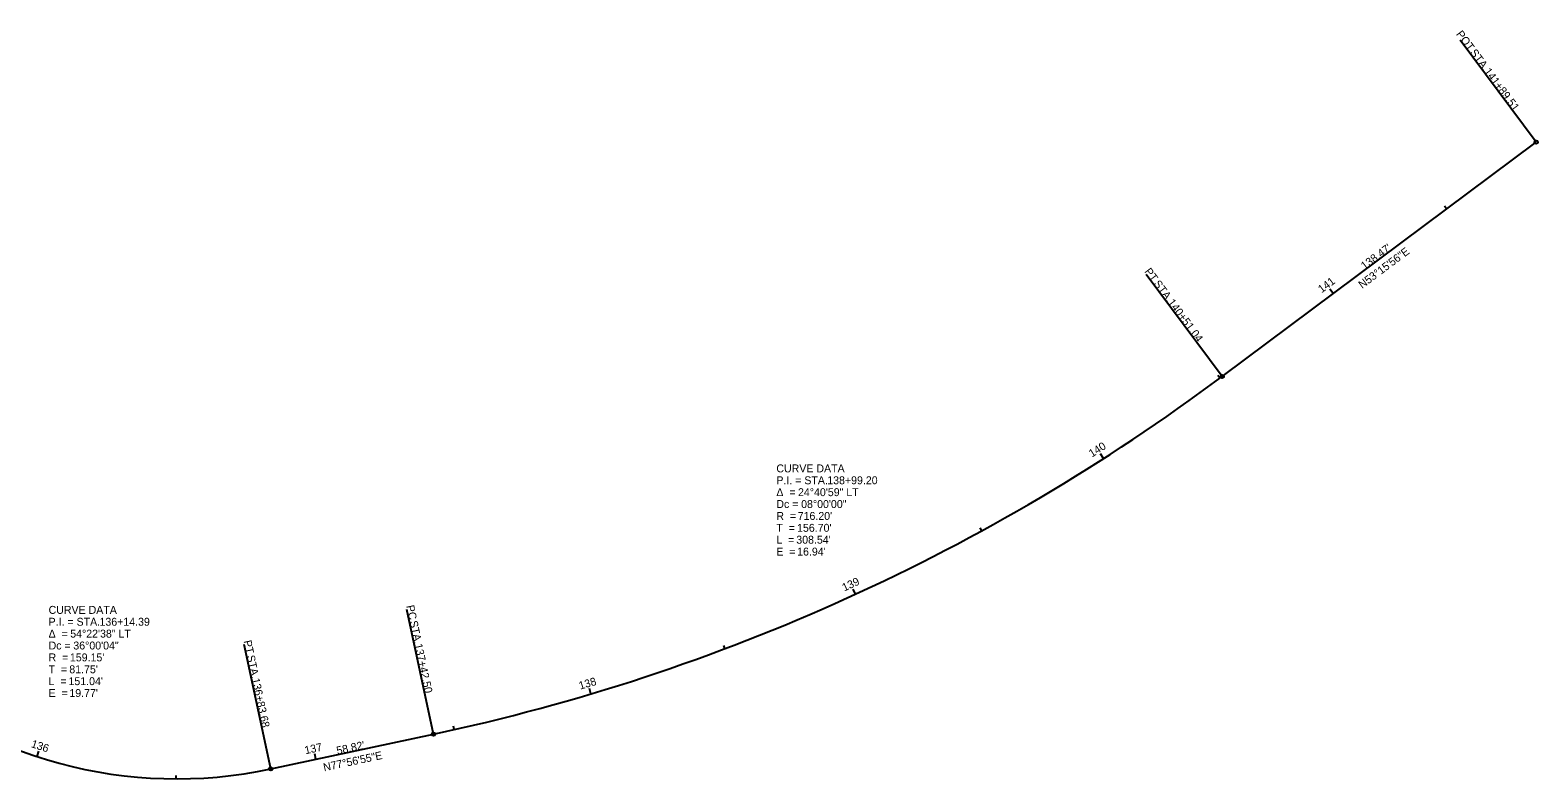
# Model space of a CAD drawing. Extents: x 1926907 to 1928253, y 199360 to 200380.
# Drawn here: x 1927721 to 1928253, y 199720 to 199984 of the extents above; entities that cross this region are included whole.
import ezdxf

# ---------------------------------------------------------------- set-up
doc = ezdxf.new("R2010")
doc.units = 0
for name, color, linetype in [('RW_X_CL', 7, 'Continuous'), ('RW_X_CL_100_Bearings', 7, 'Continuous'), ('RW_X_CL_100_Cardinal_Points', 7, 'Continuous'), ('RW_X_CL_100_Curve_Data', 7, 'Continuous'), ('RW_X_CL_100_Distances', 7, 'Continuous'), ('RW_X_CL_100_Stations', 7, 'Continuous')]:
    doc.layers.add(name, color=color, linetype=linetype)

msp = doc.modelspace()

# ---------------------------------------------------------------- linework, layer by layer
at = {"layer": 'RW_X_CL'}
for p, q in [((1928141.93, 199862.1), (1928252.9, 199944.92)), ((1927805.57, 199723.38), (1927863.1, 199735.66))]:
    msp.add_line(p, q, dxfattribs=at)
for centre, radius, start, end in [((1927713.56, 200436.07), 716.2, 282.05144, 306.73454), ((1927772.34, 199879.02), 159.15, 227.6743, 282.0514)]:
    msp.add_arc(centre, radius, start, end, dxfattribs=at)
at = {"layer": 'RW_X_CL_100_Cardinal_Points'}
for p, q in [((1928252.9, 199944.92), (1928225.98, 199980.98)), ((1928141.93, 199862.1), (1928115.01, 199898.16)), ((1927863.1, 199735.66), (1927853.7, 199779.67)), ((1927805.57, 199723.38), (1927796.18, 199767.39))]:
    msp.add_line(p, q, dxfattribs=at)
for centre in [(1928252.9, 199944.92), (1928141.93, 199862.1), (1927863.1, 199735.66), (1927805.57, 199723.38)]:
    msp.add_circle(centre, 0.6, dxfattribs=at)
at = {"layer": 'RW_X_CL_100_Stations'}
for p, q in [((1928221.23, 199921.29), (1928220.51, 199922.25)), ((1928181.16, 199891.38), (1928179.96, 199892.98)), ((1928141.09, 199861.48), (1928140.37, 199862.44)), ((1928099.97, 199833.05), (1928098.89, 199834.74)), ((1928056.96, 199807.57), (1928056.39, 199808.62)), ((1928012.28, 199785.15), (1928011.45, 199786.96)), ((1927966.15, 199765.89), (1927965.72, 199767.02)), ((1927918.78, 199749.91), (1927918.21, 199751.82)), ((1927870.42, 199737.26), (1927870.16, 199738.43)), ((1927722.96, 199727.72), (1927723.58, 199729.63)), ((1927821.53, 199726.78), (1927821.11, 199728.74)), ((1927772.14, 199719.87), (1927772.14, 199721.07))]:
    msp.add_line(p, q, dxfattribs=at)

# ---------------------------------------------------------------- texts
at = {"layer": 'RW_X_CL_100_Bearings'}
for s, rotation, p in [('N53°15\'56"E', 36.7345, (1928191.37, 199893.01)), ('N77°56\'55"E', 12.0514, (1927824.46, 199722.5))]:
    msp.add_text(s, height=2.8, rotation=rotation, dxfattribs=at).set_placement(p)
at = {"layer": 'RW_X_CL_100_Cardinal_Points'}
for s, rotation, p in [('POT', 306.7345, (1928224.48, 199983.06)), (' STA. ', 306.7345, (1928228.75, 199977.34)), ('141+89.51', 306.7345, (1928234.32, 199969.87)), ('PT', 306.7345, (1928114.31, 199899.17)), (' STA. ', 306.7345, (1928116.91, 199895.68)), ('140+51.04', 306.7345, (1928122.49, 199888.21)), ('PC', 282.0514, (1927853.46, 199780.98)), (' STA. ', 282.0514, (1927854.42, 199776.48)), ('PT', 282.0514, (1927795.96, 199768.56)), ('137+42.50', 282.0514, (1927856.36, 199767.37)), (' STA. ', 282.0514, (1927796.87, 199764.31)), ('136+83.68', 282.0514, (1927798.82, 199755.19))]:
    msp.add_text(s, height=2.8, rotation=rotation, dxfattribs=at).set_placement(p)
at = {"layer": 'RW_X_CL_100_Curve_Data'}
for s, p in [('CURVE DATA', (1927984.31, 199828.19)), ('P.I. = STA. ', (1927984.31, 199823.99)), ('138+99.20', (1928002.3, 199823.99)), ('Δ  = ', (1927984.31, 199819.79)), ('24°40\'59" LT', (1927991.96, 199819.79)), ('Dc = ', (1927984.31, 199815.59)), ('R  = ', (1927984.31, 199811.39)), ("716.20'", (1927991.85, 199811.39)), ('08°00\'00"', (1927993.06, 199815.59)), ('T  = ', (1927984.31, 199807.19)), ("156.70'", (1927991.63, 199807.19)), ('L  = ', (1927984.31, 199802.99)), ("308.54'", (1927991.35, 199802.99)), ('E  = ', (1927984.31, 199798.79)), ("16.94'", (1927991.66, 199798.79)), ('CURVE DATA', (1927727.04, 199778.19)), ('P.I. = STA. ', (1927727.04, 199773.99)), ('136+14.39', (1927745.03, 199773.99)), ('Δ  = ', (1927727.04, 199769.79)), ('54°22\'38" LT', (1927734.68, 199769.79)), ('Dc = ', (1927727.04, 199765.59)), ('36°00\'04"', (1927735.78, 199765.59)), ('R  = ', (1927727.04, 199761.39)), ("159.15'", (1927734.57, 199761.39)), ('T  = ', (1927727.04, 199757.19)), ('L  = ', (1927727.04, 199752.99)), ("151.04'", (1927734.07, 199752.99)), ("81.75'", (1927734.36, 199757.19)), ('E  = ', (1927727.04, 199748.79)), ("19.77'", (1927734.38, 199748.79))]:
    msp.add_text(s, height=2.8, dxfattribs=at).set_placement(p)
at = {"layer": 'RW_X_CL_100_Distances'}
for s, rotation, p in [("138.47'", 36.7345, (1928192.23, 199899.69)), ("58.82'", 12.0514, (1927829.12, 199728.44))]:
    msp.add_text(s, height=2.8, rotation=rotation, dxfattribs=at).set_placement(p)
at = {"layer": 'RW_X_CL_100_Stations'}
for s, rotation, p in [('141', 36.7345, (1928177.08, 199891.46)), ('140', 32.6511, (1928095.87, 199833.4)), ('139', 24.6511, (1928008.31, 199786.07)), ('138', 16.6511, (1927914.95, 199751.37)), ('136', 341.9245, (1927720.65, 199731.11)), ('137', 12.0514, (1927817.84, 199728.55))]:
    msp.add_text(s, height=2.8, rotation=rotation, dxfattribs=at).set_placement(p)

doc.saveas('drawing.dxf')
